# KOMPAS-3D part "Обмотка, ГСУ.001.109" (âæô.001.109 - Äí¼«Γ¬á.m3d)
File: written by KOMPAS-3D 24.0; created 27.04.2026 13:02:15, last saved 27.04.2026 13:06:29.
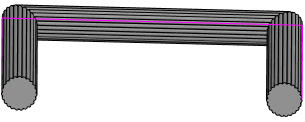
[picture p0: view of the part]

Document properties: Автор: User7; Полное имя файла: C:\Users\User7\Desktop\Двигатель мясорубки\ГСУ.001.109 - Обмотка.m3d

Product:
- Part/product: Обмотка  | designation ГСУ.001.109
    Масса: 0.002133

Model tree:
1. Эскиз:1
2. Эскиз:2
3. Элемент по траектории:1
     Длина траектории = 66.5

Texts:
  ГСУ.001.109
